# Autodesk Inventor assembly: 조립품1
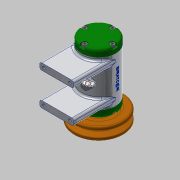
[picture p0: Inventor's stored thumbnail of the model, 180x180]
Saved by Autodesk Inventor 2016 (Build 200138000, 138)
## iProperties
Created: 2020-07
Part Number: 조립품1
Material: 일반
Document SubType Name: Assembly
Designer: 605-17
Author: 605-17
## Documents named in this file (15)
- C:\Users\605-17\Desktop\700706V1006\조립품1.iam
- C:\Users\605-17\Desktop\700706V1006\본체.ipt
- C:\Users\605-17\Desktop\700706V1006\베어링 6002.ipt
- C:\Users\605-17\Desktop\700706V1006\앞커버.ipt
- C:\Users\605-17\Desktop\700706V1006\뒤커버.ipt
- C:\Users\605-17\Desktop\700706V1006\축.ipt
- C:\Users\605-17\Desktop\700706V1006\오일 실 15 25 7.ipt
- C:\Users\605-17\Desktop\700706V1006\볼트 M4x12.ipt
- C:\Users\605-17\Desktop\700706V1006\V벨트풀리.ipt
- C:\Users\605-17\Desktop\700706V1006\Ű 3x3x12.ipt
- C:\Users\605-17\Desktop\700706V1006\와셔 8x17.ipt
- C:\Users\605-17\Desktop\700706V1006\스프링와셔 8.ipt
- C:\Users\605-17\Desktop\700706V1006\너트 M8.ipt
- C:\Users\605-17\Desktop\700706V1006\와셔 6x11.5.ipt
- C:\Users\605-17\Desktop\700706V1006\볼트 M6x8.ipt
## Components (2 placed, 2 different names)
1. V벨트풀리:1
2. Ű 3x3x12:1
